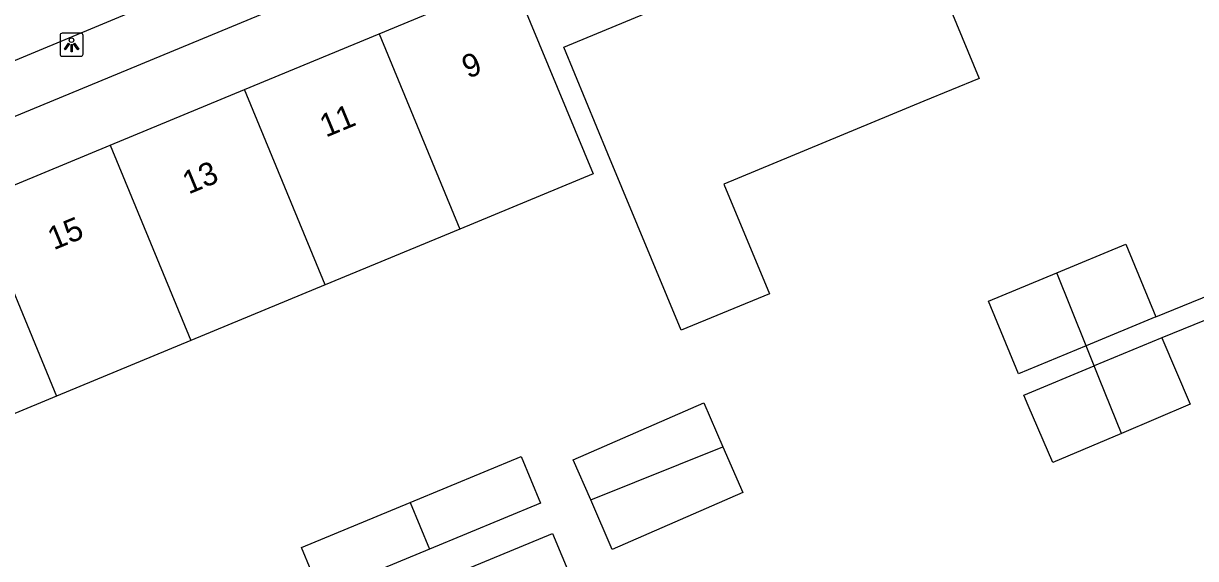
# Model space of a CAD drawing. Extents: x 162990 to 165007, y 383433 to 384336.
# Drawn here: x 163902.7 to 163953.5, y 383884.6 to 383907.8 of the extents above; entities that cross this region are included whole.
import ezdxf

# ---------------------------------------------------------------- set-up
doc = ezdxf.new("R2010")
doc.units = 0
for name, color, linetype in [('IMGEO_Lichtpunt', 7, 'Continuous'), ('IMGEO_Pand', 7, 'Continuous'), ('IMGEO_Pand_nummerreeks', 7, 'Continuous'), ('IMGEO_Rijbaan_lokaal_open', 7, 'Continuous'), ('IMGEO_Voetpad_open', 7, 'Continuous')]:
    doc.layers.add(name, color=color, linetype=linetype)

msp = doc.modelspace()

# ---------------------------------------------------------------- linework, layer by layer
at = {"layer": 'IMGEO_Lichtpunt'}
for p, q in [((163904.333, 383907.238), (163904.333, 383906.431)), ((163904.333, 383907.238), (163904.333, 383906.431)), ((163905.235, 383907.333), (163904.427, 383907.333)), ((163905.235, 383907.333), (163904.427, 383907.333)), ((163905.329, 383906.431), (163905.329, 383907.238)), ((163905.329, 383906.431), (163905.329, 383907.238)), ((163904.427, 383906.337), (163905.235, 383906.337)), ((163904.427, 383906.337), (163905.235, 383906.337))]:
    msp.add_line(p, q, dxfattribs=at)
for points in [[(163904.707, 383906.902), (163904.746, 383906.874), (163904.558, 383906.612), (163904.52, 383906.639), (163904.707, 383906.902)], [(163904.809, 383906.854), (163904.856, 383906.854), (163904.856, 383906.532), (163904.809, 383906.532), (163904.809, 383906.854)], [(163904.919, 383906.874), (163904.957, 383906.901), (163905.144, 383906.639), (163905.105, 383906.611), (163904.919, 383906.874)]]:
    msp.add_lwpolyline(points, dxfattribs=at)
msp.add_circle((163904.832, 383907.036), 0.0994, dxfattribs=at)
for centre, start, end in [((163904.427, 383907.238), 90, 180), ((163904.427, 383907.238), 90, 180), ((163905.235, 383907.238), 0, 90), ((163905.235, 383907.238), 0, 90), ((163904.427, 383906.431), 180, 270), ((163904.427, 383906.431), 180, 270), ((163905.235, 383906.431), 270, 0), ((163905.235, 383906.431), 270, 360)]:
    msp.add_arc(centre, 0.0946, start, end, dxfattribs=at)
at = {"layer": 'IMGEO_Pand'}
for points in [[(163918.161, 383907.311), (163923.936, 383909.702), (163927.44, 383901.238), (163921.666, 383898.847)], [(163942.69, 383908.945), (163944.168, 383905.374), (163941.778, 383904.385), (163933.11, 383900.797), (163935.075, 383896.047), (163931.249, 383894.463), (163928.082, 383902.114), (163926.17, 383906.733), (163929.7, 383908.194)], [(163912.322, 383904.893), (163918.161, 383907.311)], [(163918.161, 383907.311), (163921.666, 383898.847)], [(163906.5, 383902.482), (163912.322, 383904.893)], [(163915.826, 383896.429), (163912.322, 383904.893)], [(163900.679, 383900.072), (163906.5, 383902.482)], [(163906.5, 383902.482), (163910.005, 383894.018)], [(163900.679, 383900.072), (163904.184, 383891.608)], [(163921.666, 383898.847), (163915.826, 383896.429)], [(163947.536, 383896.957), (163950.527, 383898.195), (163951.832, 383895.04)], [(163948.807, 383893.788), (163945.874, 383892.574), (163944.569, 383895.729), (163947.536, 383896.957)], [(163948.807, 383893.788), (163947.536, 383896.957)], [(163915.826, 383896.429), (163910.005, 383894.018)], [(163951.832, 383895.04), (163948.807, 383893.788)], [(163910.005, 383894.018), (163904.184, 383891.608)], [(163952.089, 383894.13), (163949.158, 383892.914)], [(163952.089, 383894.13), (163953.311, 383891.263), (163950.331, 383889.992)], [(163950.331, 383889.992), (163947.355, 383888.723), (163946.299, 383891.2), (163946.105, 383891.648), (163949.158, 383892.914)], [(163950.331, 383889.992), (163949.39, 383892.338), (163949.158, 383892.914)], [(163904.184, 383891.608), (163898.226, 383889.141)], [(163927.335, 383887.105), (163926.578, 383888.844), (163932.237, 383891.309), (163933.063, 383889.412)], [(163927.335, 383887.105), (163933.063, 383889.412)], [(163933.063, 383889.412), (163933.927, 383887.43), (163928.268, 383884.965), (163927.335, 383887.105)], [(163919.507, 383886.994), (163924.321, 383888.987), (163925.16, 383886.962), (163920.352, 383884.971)], [(163920.352, 383884.971), (163915.637, 383883.019), (163914.798, 383885.044), (163919.507, 383886.994)], [(163919.507, 383886.994), (163920.352, 383884.971)], [(163920.894, 383883.674), (163925.682, 383885.656), (163926.493, 383883.711), (163921.674, 383881.716)]]:
    msp.add_lwpolyline(points, dxfattribs=at)
at = {"layer": 'IMGEO_Rijbaan_lokaal_open'}
msp.add_lwpolyline([(163892.691, 383902.14), (163982.692, 383939.577)], dxfattribs=at)
at = {"layer": 'IMGEO_Voetpad_open'}
for points in [[(163964.512, 383929.456), (163893.635, 383900.12)], [(163951.832, 383895.04), (163962.963, 383899.576)], [(163957.637, 383896.381), (163952.089, 383894.13)], [(163949.158, 383892.914), (163948.807, 383893.788)]]:
    msp.add_lwpolyline(points, dxfattribs=at)

# ---------------------------------------------------------------- texts
at = {"layer": 'IMGEO_Pand_nummerreeks'}
for s, p in [('9', (163922.015, 383905.356)), ('11', (163915.852, 383902.806)), ('13', (163909.904, 383900.342)), ('15', (163904.061, 383897.923))]:
    msp.add_text(s, height=1, rotation=22.4929, dxfattribs=at).set_placement(p)

doc.saveas('drawing.dxf')
